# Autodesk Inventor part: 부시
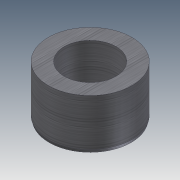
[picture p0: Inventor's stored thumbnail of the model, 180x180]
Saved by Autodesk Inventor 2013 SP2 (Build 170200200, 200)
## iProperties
Company: 한국ATC센터
Created: 2014-11
Part Number: 부시
Document SubType Name: Modeling
Designer: KYOUNG IL JANG
Density: 7.86 g/cm^3
Material: 강, 연강
Mass: 167.601 g
Surface Area: 70.0223 cm^2
Volume: 21.3233 cm^3
Author: KYOUNG IL JANG
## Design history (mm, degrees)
sketch "스케치1"
  geometry: C1 r 21 at (0, 0); C2 r 13 at (0, 0); 1 further point
  constraints: 2 centre point, 2 coincident
  dimensions: "d4" = 26 diameter of C2; "d5" = 42 diameter of C1
extrude "돌출1" new body sketch "스케치1" distance "d0" = 25; taper "d1" = 0 deg
chamfer "모따기1" distance "d6" = 1.5; stored, may be unused: second distance "d7" = 2, angle "d8" = 15 deg
node "솔리드1"
